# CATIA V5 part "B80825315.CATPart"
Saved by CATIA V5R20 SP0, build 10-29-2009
Part number: B80825315
Revision: 4
Definition: design
Nomenclature: B80825315
Source: made
Description: NOT SPECIFIED
Bounding box of the stored display mesh (mm): x -15 to 15, y -15 to 15, z 0 to 315
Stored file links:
  C:\Users\Raffaele\Desktop\3D X SITO CF\BOLEX\4-PILLAR REF 808\B80825315.CATPart
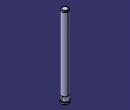
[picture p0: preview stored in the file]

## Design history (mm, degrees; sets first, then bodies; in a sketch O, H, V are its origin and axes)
Body1 "MANIFOLD_SOLID_BREP #450" (main body)
  Solid1: solid without history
